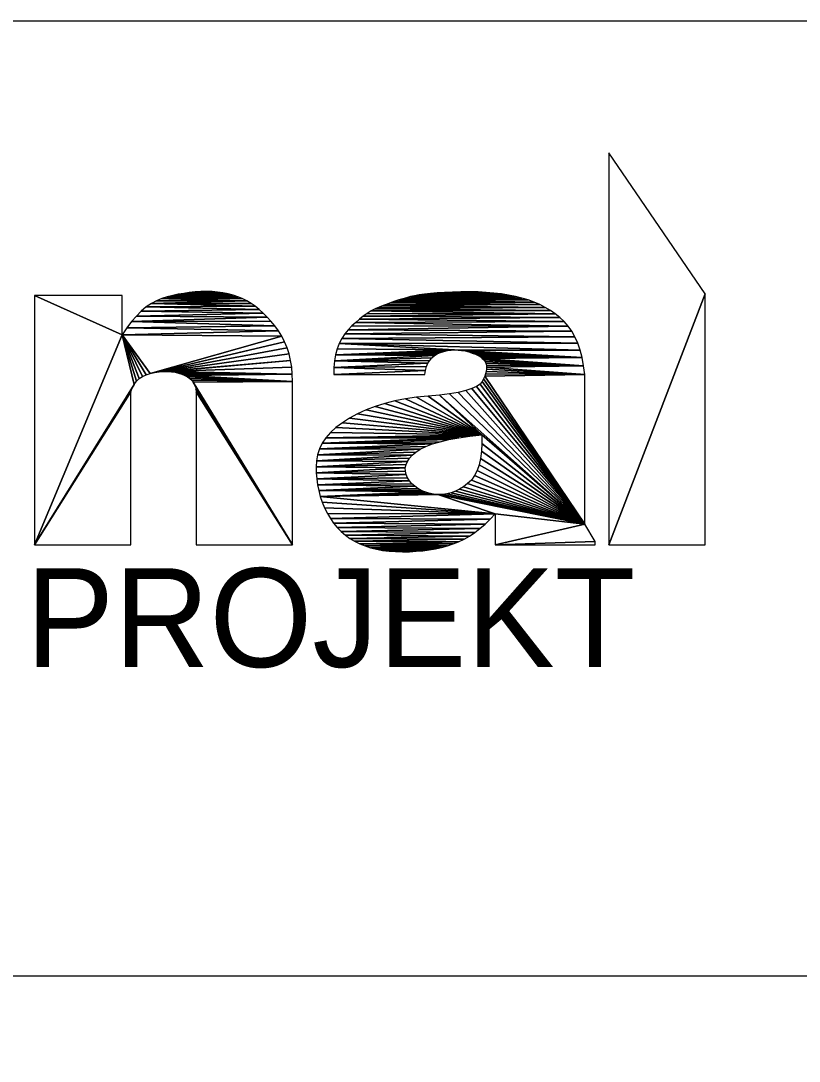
# Model space of a CAD drawing. Extents: x -630 to 5777, y 380 to 2087.
# Drawn here: x -160.3 to -142.19, y 418.03 to 442.23 of the extents above; entities that cross this region are included whole.
import ezdxf

# ---------------------------------------------------------------- set-up
doc = ezdxf.new("R2010")
doc.units = 0
doc.layers.add('Vrstva 1', color=7, linetype='Continuous')

msp = doc.modelspace()

# ---------------------------------------------------------------- linework, layer by layer
for points in [[(-180, 442.226), (-15, 442.226), (-15, 390), (-180, 390)], [(-146.62, 439.158), (-146.62, 430.038), (-144.38, 435.878)], [(-156.638, 435.864), (-156.766, 435.836), (-155.363, 435.846)], [(-155.363, 435.846), (-156.766, 435.836), (-155.252, 435.808)], [(-156.509, 435.886), (-156.638, 435.864), (-155.478, 435.876)], [(-155.478, 435.876), (-156.638, 435.864), (-155.363, 435.846)], [(-156.379, 435.904), (-156.509, 435.886), (-155.597, 435.9)], [(-155.597, 435.9), (-156.509, 435.886), (-155.478, 435.876)], [(-156.247, 435.918), (-156.379, 435.904), (-155.721, 435.916)], [(-155.721, 435.916), (-156.379, 435.904), (-155.597, 435.9)], [(-156.115, 435.926), (-156.247, 435.918), (-155.721, 435.916)], [(-155.981, 435.928), (-156.115, 435.926), (-155.849, 435.926)], [(-155.849, 435.926), (-156.115, 435.926), (-155.721, 435.916)], [(-151.03, 435.85), (-151.141, 435.832), (-148.953, 435.848)], [(-148.953, 435.848), (-151.141, 435.832), (-148.794, 435.816)], [(-150.905, 435.868), (-151.03, 435.85), (-148.953, 435.848)], [(-150.766, 435.882), (-150.905, 435.868), (-149.119, 435.874)], [(-149.119, 435.874), (-150.905, 435.868), (-148.953, 435.848)], [(-150.611, 435.896), (-150.766, 435.882), (-149.293, 435.894)], [(-149.293, 435.894), (-150.766, 435.882), (-149.119, 435.874)], [(-150.442, 435.906), (-150.611, 435.896), (-149.293, 435.894)], [(-150.258, 435.914), (-150.442, 435.906), (-149.474, 435.91)], [(-149.474, 435.91), (-150.442, 435.906), (-149.293, 435.894)], [(-150.059, 435.92), (-150.258, 435.914), (-149.661, 435.918)], [(-149.661, 435.918), (-150.258, 435.914), (-149.474, 435.91)], [(-149.857, 435.922), (-150.059, 435.92), (-149.661, 435.918)], [(-144.38, 435.878), (-146.62, 430.038), (-144.38, 430.038)], [(-157.94, 434.918), (-157.94, 435.838), (-159.98, 435.838)], [(-159.98, 435.838), (-159.98, 430.038), (-157.94, 434.918)], [(-157.263, 435.652), (-157.382, 435.57), (-154.847, 435.586)], [(-157.142, 435.716), (-157.263, 435.652), (-155.044, 435.712)], [(-155.044, 435.712), (-157.263, 435.652), (-154.944, 435.654)], [(-154.944, 435.654), (-157.263, 435.652), (-154.847, 435.586)], [(-155.146, 435.764), (-157.142, 435.716), (-155.044, 435.712)], [(-157.018, 435.764), (-157.142, 435.716), (-155.146, 435.764)], [(-156.892, 435.802), (-157.018, 435.764), (-155.146, 435.764)], [(-156.766, 435.836), (-156.892, 435.802), (-155.252, 435.808)], [(-155.252, 435.808), (-156.892, 435.802), (-155.146, 435.764)], [(-151.871, 435.602), (-151.965, 435.566), (-148.1, 435.558)], [(-151.779, 435.638), (-151.871, 435.602), (-148.226, 435.624)], [(-148.226, 435.624), (-151.871, 435.602), (-148.1, 435.558)], [(-151.687, 435.672), (-151.779, 435.638), (-148.226, 435.624)], [(-151.595, 435.702), (-151.687, 435.672), (-148.358, 435.682)], [(-148.358, 435.682), (-151.687, 435.672), (-148.226, 435.624)], [(-151.505, 435.732), (-151.595, 435.702), (-148.358, 435.682)], [(-151.415, 435.76), (-151.505, 435.732), (-148.497, 435.734)], [(-148.497, 435.734), (-151.505, 435.732), (-148.358, 435.682)], [(-151.325, 435.786), (-151.415, 435.76), (-148.642, 435.778)], [(-148.642, 435.778), (-151.415, 435.76), (-148.497, 435.734)], [(-151.237, 435.81), (-151.325, 435.786), (-148.642, 435.778)], [(-151.141, 435.832), (-151.237, 435.81), (-148.794, 435.816)], [(-148.794, 435.816), (-151.237, 435.81), (-148.642, 435.778)], [(-157.498, 435.472), (-157.612, 435.358), (-154.659, 435.428)], [(-154.659, 435.428), (-157.612, 435.358), (-154.568, 435.336)], [(-157.382, 435.57), (-157.498, 435.472), (-154.752, 435.512)], [(-154.752, 435.512), (-157.498, 435.472), (-154.659, 435.428)], [(-154.847, 435.586), (-157.382, 435.57), (-154.752, 435.512)], [(-152.242, 435.42), (-152.332, 435.358), (-147.866, 435.408)], [(-147.866, 435.408), (-152.332, 435.358), (-147.759, 435.322)], [(-152.15, 435.476), (-152.242, 435.42), (-147.866, 435.408)], [(-152.058, 435.524), (-152.15, 435.476), (-147.98, 435.486)], [(-147.98, 435.486), (-152.15, 435.476), (-147.866, 435.408)], [(-151.965, 435.566), (-152.058, 435.524), (-148.1, 435.558)], [(-148.1, 435.558), (-152.058, 435.524), (-147.98, 435.486)], [(-157.724, 435.228), (-157.833, 435.082), (-154.393, 435.128)], [(-154.393, 435.128), (-157.833, 435.082), (-154.308, 435.012)], [(-157.612, 435.358), (-157.724, 435.228), (-154.568, 435.336)], [(-154.568, 435.336), (-157.724, 435.228), (-154.479, 435.236)], [(-154.479, 435.236), (-157.724, 435.228), (-154.393, 435.128)], [(-152.596, 435.13), (-152.682, 435.04), (-147.565, 435.126)], [(-147.565, 435.126), (-152.682, 435.04), (-147.481, 435.008)], [(-152.509, 435.212), (-152.596, 435.13), (-147.565, 435.126)], [(-152.421, 435.288), (-152.509, 435.212), (-147.658, 435.23)], [(-147.658, 435.23), (-152.509, 435.212), (-147.565, 435.126)], [(-152.332, 435.358), (-152.421, 435.288), (-147.759, 435.322)], [(-147.759, 435.322), (-152.421, 435.288), (-147.658, 435.23)], [(-157.94, 434.918), (-159.98, 430.038), (-157.662, 433.77)], [(-157.833, 435.082), (-157.94, 434.918), (-154.308, 435.012)], [(-154.308, 435.012), (-157.94, 434.918), (-154.229, 434.888)], [(-157.94, 434.918), (-157.291, 434.024), (-154.229, 434.888)], [(-157.94, 434.918), (-157.385, 433.994), (-157.291, 434.024)], [(-157.94, 434.918), (-157.469, 433.952), (-157.385, 433.994)], [(-157.94, 434.918), (-157.543, 433.902), (-157.469, 433.952)], [(-157.94, 434.918), (-157.607, 433.84), (-157.543, 433.902)], [(-157.94, 434.918), (-157.662, 433.77), (-157.607, 433.84)], [(-154.229, 434.888), (-157.291, 434.024), (-154.161, 434.758)], [(-152.763, 434.942), (-152.832, 434.836), (-147.407, 434.876)], [(-147.407, 434.876), (-152.832, 434.836), (-147.343, 434.73)], [(-152.682, 435.04), (-152.763, 434.942), (-147.481, 435.008)], [(-147.481, 435.008), (-152.763, 434.942), (-147.407, 434.876)], [(-154.161, 434.758), (-157.291, 434.024), (-157.187, 434.046)], [(-154.161, 434.758), (-157.187, 434.046), (-154.104, 434.622)], [(-152.89, 434.72), (-152.938, 434.594), (-150.209, 434.57)], [(-152.832, 434.836), (-152.89, 434.72), (-147.343, 434.73)], [(-147.343, 434.73), (-152.89, 434.72), (-147.288, 434.568)], [(-152.89, 434.72), (-150.209, 434.57), (-147.288, 434.568)], [(-154.104, 434.622), (-157.187, 434.046), (-154.058, 434.478)], [(-154.058, 434.478), (-157.187, 434.046), (-157.081, 434.058)], [(-154.058, 434.478), (-157.081, 434.058), (-154.022, 434.328)], [(-152.975, 434.46), (-153.001, 434.314), (-150.678, 434.438)], [(-150.678, 434.438), (-153.001, 434.314), (-150.737, 434.388)], [(-152.938, 434.594), (-152.975, 434.46), (-150.209, 434.57)], [(-150.209, 434.57), (-152.975, 434.46), (-150.291, 434.566)], [(-150.291, 434.566), (-152.975, 434.46), (-150.373, 434.554)], [(-150.373, 434.554), (-152.975, 434.46), (-150.454, 434.536)], [(-150.454, 434.536), (-152.975, 434.46), (-150.535, 434.512)], [(-150.535, 434.512), (-152.975, 434.46), (-150.611, 434.48)], [(-150.611, 434.48), (-152.975, 434.46), (-150.678, 434.438)], [(-150.209, 434.57), (-150.127, 434.568), (-147.288, 434.568)], [(-150.127, 434.568), (-150.044, 434.56), (-147.288, 434.568)], [(-147.288, 434.568), (-150.044, 434.56), (-147.243, 434.392)], [(-150.044, 434.56), (-149.96, 434.546), (-147.243, 434.392)], [(-149.96, 434.546), (-149.876, 434.524), (-147.243, 434.392)], [(-149.876, 434.524), (-149.796, 434.498), (-147.243, 434.392)], [(-149.796, 434.498), (-149.724, 434.47), (-147.243, 434.392)], [(-149.724, 434.47), (-149.662, 434.44), (-147.243, 434.392)], [(-149.662, 434.44), (-149.608, 434.408), (-147.243, 434.392)], [(-149.608, 434.408), (-149.563, 434.374), (-147.243, 434.392)], [(-147.243, 434.392), (-149.563, 434.374), (-147.207, 434.202)], [(-154.022, 434.328), (-157.081, 434.058), (-156.98, 434.066)], [(-154.022, 434.328), (-156.98, 434.066), (-156.885, 434.066)], [(-154.022, 434.328), (-156.885, 434.066), (-153.998, 434.17)], [(-153.998, 434.17), (-156.885, 434.066), (-153.984, 434.008)], [(-153.016, 434.16), (-153.02, 433.998), (-150.885, 434.094)], [(-153.001, 434.314), (-153.016, 434.16), (-150.828, 434.26)], [(-150.828, 434.26), (-153.016, 434.16), (-150.861, 434.182)], [(-150.861, 434.182), (-153.016, 434.16), (-150.885, 434.094)], [(-150.737, 434.388), (-153.001, 434.314), (-150.787, 434.328)], [(-150.787, 434.328), (-153.001, 434.314), (-150.828, 434.26)], [(-149.563, 434.374), (-149.526, 434.338), (-147.207, 434.202)], [(-149.526, 434.338), (-149.499, 434.3), (-147.207, 434.202)], [(-149.499, 434.3), (-149.48, 434.26), (-147.207, 434.202)], [(-149.48, 434.26), (-149.468, 434.216), (-147.207, 434.202)], [(-149.468, 434.216), (-149.463, 434.17), (-147.207, 434.202)], [(-149.463, 434.17), (-149.464, 434.122), (-147.18, 433.998)], [(-147.207, 434.202), (-149.463, 434.17), (-147.18, 433.998)], [(-156.885, 434.066), (-156.794, 434.062), (-153.984, 434.008)], [(-156.794, 434.062), (-156.709, 434.05), (-153.984, 434.008)], [(-156.709, 434.05), (-156.63, 434.032), (-153.984, 434.008)], [(-156.63, 434.032), (-156.555, 434.008), (-153.984, 434.008)], [(-156.555, 434.008), (-156.486, 433.978), (-153.984, 434.008)], [(-153.984, 434.008), (-156.486, 433.978), (-153.98, 433.838)], [(-156.486, 433.978), (-156.424, 433.944), (-153.98, 433.838)], [(-156.424, 433.944), (-156.37, 433.906), (-153.98, 433.838)], [(-150.885, 434.094), (-153.02, 433.998), (-150.9, 433.998)], [(-149.506, 433.96), (-149.532, 433.9), (-147.18, 430.518)], [(-149.486, 434.016), (-149.506, 433.96), (-147.18, 433.998)], [(-147.18, 433.998), (-149.506, 433.96), (-147.18, 430.518)], [(-149.472, 434.07), (-149.486, 434.016), (-147.18, 433.998)], [(-149.464, 434.122), (-149.472, 434.07), (-147.18, 433.998)], [(-157.662, 433.77), (-159.98, 430.038), (-157.706, 433.688)], [(-157.706, 433.688), (-159.98, 430.038), (-157.74, 433.598)], [(-156.37, 433.906), (-156.324, 433.864), (-153.98, 433.838)], [(-156.324, 433.864), (-156.287, 433.818), (-153.98, 433.838)], [(-153.98, 433.838), (-156.287, 433.818), (-153.98, 430.038)], [(-156.287, 433.818), (-156.258, 433.768), (-153.98, 430.038)], [(-156.258, 433.768), (-156.237, 433.716), (-153.98, 430.038)], [(-156.237, 433.716), (-156.225, 433.658), (-153.98, 430.038)], [(-149.807, 433.67), (-149.949, 433.624), (-147.18, 430.518)], [(-149.696, 433.72), (-149.807, 433.67), (-147.18, 430.518)], [(-149.615, 433.776), (-149.696, 433.72), (-147.18, 430.518)], [(-149.564, 433.838), (-149.615, 433.776), (-147.18, 430.518)], [(-149.532, 433.9), (-149.564, 433.838), (-147.18, 430.518)], [(-157.74, 433.598), (-159.98, 430.038), (-157.74, 430.038)], [(-156.225, 433.658), (-156.22, 433.598), (-153.98, 430.038)], [(-156.22, 433.598), (-156.22, 430.038), (-153.98, 430.038)], [(-151.35, 433.432), (-151.598, 433.384), (-149.576, 432.594)], [(-151.091, 433.468), (-151.35, 433.432), (-149.576, 432.594)], [(-150.819, 433.496), (-151.091, 433.468), (-149.576, 432.594)], [(-150.556, 433.52), (-150.819, 433.496), (-149.576, 432.594)], [(-150.323, 433.55), (-150.556, 433.52), (-147.18, 430.518)], [(-150.556, 433.52), (-149.576, 432.594), (-147.18, 430.518)], [(-150.121, 433.584), (-150.323, 433.55), (-147.18, 430.518)], [(-149.949, 433.624), (-150.121, 433.584), (-147.18, 430.518)], [(-152.055, 433.256), (-152.266, 433.176), (-149.576, 432.594)], [(-151.833, 433.326), (-152.055, 433.256), (-149.576, 432.594)], [(-151.598, 433.384), (-151.833, 433.326), (-149.576, 432.594)], [(-152.65, 432.986), (-152.819, 432.878), (-149.576, 432.594)], [(-152.464, 433.086), (-152.65, 432.986), (-149.576, 432.594)], [(-152.266, 433.176), (-152.464, 433.086), (-149.576, 432.594)], [(-152.967, 432.766), (-153.095, 432.648), (-149.576, 432.594)], [(-152.819, 432.878), (-152.967, 432.766), (-149.576, 432.594)], [(-150.11, 432.526), (-153.287, 432.4), (-150.339, 432.484)], [(-153.201, 432.526), (-153.287, 432.4), (-150.11, 432.526)], [(-150.339, 432.484), (-153.287, 432.4), (-150.544, 432.436)], [(-153.095, 432.648), (-153.201, 432.526), (-149.576, 432.594)], [(-149.576, 432.594), (-153.201, 432.526), (-149.855, 432.562)], [(-149.855, 432.562), (-153.201, 432.526), (-150.11, 432.526)], [(-149.576, 432.594), (-149.571, 432.394), (-147.18, 430.518)], [(-153.352, 432.27), (-153.396, 432.134), (-151.005, 432.264)], [(-151.005, 432.264), (-153.396, 432.134), (-151.108, 432.196)], [(-153.287, 432.4), (-153.352, 432.27), (-150.723, 432.384)], [(-150.723, 432.384), (-153.352, 432.27), (-150.876, 432.326)], [(-150.876, 432.326), (-153.352, 432.27), (-151.005, 432.264)], [(-150.544, 432.436), (-153.287, 432.4), (-150.723, 432.384)], [(-149.571, 432.394), (-149.58, 432.212), (-147.18, 430.518)], [(-153.419, 431.994), (-153.427, 431.854), (-151.306, 431.978)], [(-151.306, 431.978), (-153.427, 431.854), (-151.338, 431.904)], [(-153.396, 432.134), (-153.419, 431.994), (-151.191, 432.124)], [(-151.191, 432.124), (-153.419, 431.994), (-151.257, 432.052)], [(-151.257, 432.052), (-153.419, 431.994), (-151.306, 431.978)], [(-151.108, 432.196), (-153.396, 432.134), (-151.191, 432.124)], [(-149.602, 432.046), (-149.636, 431.898), (-147.18, 430.518)], [(-149.58, 432.212), (-149.602, 432.046), (-147.18, 430.518)], [(-151.338, 431.904), (-153.427, 431.854), (-151.354, 431.828)], [(-153.427, 431.854), (-153.426, 431.714), (-151.354, 431.828)], [(-151.354, 431.828), (-153.426, 431.714), (-151.353, 431.752)], [(-151.353, 431.752), (-153.426, 431.714), (-151.335, 431.676)], [(-149.684, 431.764), (-149.744, 431.646), (-147.18, 430.518)], [(-149.636, 431.898), (-149.684, 431.764), (-147.18, 430.518)], [(-153.426, 431.714), (-153.416, 431.574), (-151.335, 431.676)], [(-151.335, 431.676), (-153.416, 431.574), (-151.301, 431.598)], [(-151.301, 431.598), (-153.416, 431.574), (-151.254, 431.524)], [(-153.416, 431.574), (-153.397, 431.436), (-151.254, 431.524)], [(-151.254, 431.524), (-153.397, 431.436), (-151.199, 431.456)], [(-149.818, 431.544), (-149.904, 431.46), (-147.18, 430.518)], [(-149.744, 431.646), (-149.818, 431.544), (-147.18, 430.518)], [(-151.199, 431.456), (-153.397, 431.436), (-151.136, 431.398)], [(-153.397, 431.436), (-153.369, 431.3), (-151.136, 431.398)], [(-151.136, 431.398), (-153.369, 431.3), (-151.065, 431.346)], [(-151.065, 431.346), (-153.369, 431.3), (-150.986, 431.302)], [(-150.986, 431.302), (-153.369, 431.3), (-150.9, 431.266)], [(-153.369, 431.3), (-153.332, 431.164), (-150.9, 431.266)], [(-150.9, 431.266), (-153.332, 431.164), (-150.805, 431.238)], [(-150.289, 431.246), (-150.389, 431.22), (-147.18, 430.518)], [(-150.19, 431.282), (-150.289, 431.246), (-147.18, 430.518)], [(-150.093, 431.328), (-150.19, 431.282), (-147.18, 430.518)], [(-149.997, 431.388), (-150.093, 431.328), (-147.18, 430.518)], [(-149.904, 431.46), (-149.997, 431.388), (-147.18, 430.518)], [(-150.805, 431.238), (-153.332, 431.164), (-150.702, 431.218)], [(-150.702, 431.218), (-153.332, 431.164), (-150.596, 431.208)], [(-150.596, 431.208), (-153.332, 431.164), (-149.26, 430.758)], [(-153.332, 431.164), (-153.286, 431.03), (-149.26, 430.758)], [(-153.286, 431.03), (-153.231, 430.896), (-149.26, 430.758)], [(-150.596, 431.208), (-149.26, 430.758), (-147.18, 430.518)], [(-150.492, 431.208), (-150.596, 431.208), (-147.18, 430.518)], [(-150.389, 431.22), (-150.492, 431.208), (-147.18, 430.518)], [(-153.231, 430.896), (-153.168, 430.768), (-149.26, 430.758)], [(-153.168, 430.768), (-153.098, 430.65), (-149.26, 430.758)], [(-149.26, 430.758), (-153.098, 430.65), (-149.378, 430.634)], [(-153.098, 430.65), (-153.021, 430.538), (-149.378, 430.634)], [(-149.378, 430.634), (-153.021, 430.538), (-149.496, 430.52)], [(-153.021, 430.538), (-152.937, 430.438), (-149.496, 430.52)], [(-149.496, 430.52), (-152.937, 430.438), (-149.617, 430.418)], [(-149.26, 430.758), (-149.26, 430.038), (-147.18, 430.518)], [(-152.937, 430.438), (-152.847, 430.344), (-149.617, 430.418)], [(-149.617, 430.418), (-152.847, 430.344), (-149.739, 430.324)], [(-152.847, 430.344), (-152.749, 430.26), (-149.739, 430.324)], [(-149.739, 430.324), (-152.749, 430.26), (-149.863, 430.242)], [(-147.18, 430.518), (-149.26, 430.038), (-146.94, 430.118)], [(-152.749, 430.26), (-152.645, 430.186), (-149.863, 430.242)], [(-149.863, 430.242), (-152.645, 430.186), (-149.988, 430.17)], [(-152.645, 430.186), (-152.533, 430.12), (-149.988, 430.17)], [(-149.988, 430.17), (-152.533, 430.12), (-150.115, 430.108)], [(-152.533, 430.12), (-152.415, 430.062), (-150.115, 430.108)], [(-150.115, 430.108), (-152.415, 430.062), (-150.244, 430.058)], [(-152.415, 430.062), (-152.291, 430.012), (-150.244, 430.058)], [(-150.244, 430.058), (-152.291, 430.012), (-150.375, 430.014)], [(-146.94, 430.118), (-149.26, 430.038), (-146.94, 430.038)], [(-150.375, 430.014), (-152.291, 430.012), (-150.511, 429.976)], [(-152.291, 430.012), (-152.161, 429.97), (-150.511, 429.976)], [(-150.511, 429.976), (-152.161, 429.97), (-150.652, 429.946)], [(-152.161, 429.97), (-152.024, 429.936), (-150.652, 429.946)], [(-150.652, 429.946), (-152.024, 429.936), (-150.796, 429.92)], [(-152.024, 429.936), (-151.882, 429.908), (-150.796, 429.92)], [(-150.796, 429.92), (-151.882, 429.908), (-150.945, 429.9)], [(-151.882, 429.908), (-151.733, 429.888), (-150.945, 429.9)], [(-150.945, 429.9), (-151.733, 429.888), (-151.098, 429.886)], [(-151.733, 429.888), (-151.579, 429.878), (-151.098, 429.886)], [(-151.098, 429.886), (-151.579, 429.878), (-151.256, 429.876)], [(-151.579, 429.878), (-151.418, 429.874), (-151.256, 429.876)]]:
    msp.add_lwpolyline(points, close=True)
at = {"layer": 'Vrstva 1'}
msp.add_line((-65, 420), (-180, 420), dxfattribs=at)

# ---------------------------------------------------------------- texts
msp.add_text('PROJEKT', height=2.299).set_placement((-160.18, 427.194))

doc.saveas('drawing.dxf')
